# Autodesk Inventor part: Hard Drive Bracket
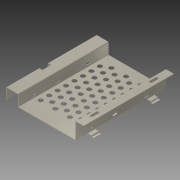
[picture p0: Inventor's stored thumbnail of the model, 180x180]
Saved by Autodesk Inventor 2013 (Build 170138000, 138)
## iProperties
Created: 2007-02
Part Number: Hard Drive Bracket
Material: Allgemein
Document SubType Name: Sheet Metal
Designer: Autodesk, Inc.
Mass: 29.7395 g
Surface Area: 618.59 cm^2
Volume: 29.7395 cm^3
Density: 1 g/cm^3
Flat Pattern Width: 16 cm
Flat Pattern Length: 21.3383 cm
Flat Pattern Area: 341.412 cm^2
Sheet Metal Rule: 1 mm
Sheet Metal Width: 160.000 mm
Sheet Metal Length: 213.383 mm
Sheet Metal Area: 34141.239 mm^2
Length: =<FLAT PATTERN LENGTH> cm
Width: =<FLAT PATTERN WIDTH> cm
Author: Autodesk, Inc.
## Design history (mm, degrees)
node "Face1"
node "Contour Flange1"
cut "Cut1" dims "d18" = 1 (= Thickness), "d19" = 0
node "Face3"
  sketch "Sketch5"
    geometry: L1 (0, 0)-(5.5, 0); L2 (6, -0.5)-(6, -0.5); L3 (7.5, -2)-(11, -2); A1 r 0.5 centre (5.5, -0.5) between (6, -0.5) and (5.5, 0); A2 r 1.5 centre (7.5, -0.5) between (6, -0.5) and (7.5, -2); 2 further points
    constraints: 6 end point, 4 point on circle, 4 point on line, 4 tangent, 2 centre point, 1 horizontal, 1 parallel, 1 perpendicular
    dimensions: "d67" = 2 distance of point (6, 0) point (6, -2); "d68" = 5 distance of point (6, -2) L3.end; "d69" = 0.5 radius of A1; "d70" = 1.5 radius of A2; "d71" = 5.5 distance of L1.start L1.end
node "Contour Flange2"
cut "Cut2" dims "d76" = 1 (= Thickness), "d77" = 0
mirror "Mirror1"
node "Contour Flange3"
cut "Cut3" dims "d101" = 1 (= Thickness), "d102" = 0
feature "iFeature1:1"
feature "iFeature2:1"
feature "iFeature3:1" dims "d118" = 3 (= d119), "d119" = 3, "d120" = 8
mirror "Mirror2"
feature "iFeature4:1"
body "Solid1"
node "Face2"
sketch "Sketch1"
  geometry: L1 (-50.5, 80)-(50.5, 80); L2 (50.5, 80)-(50.5, -80); L3 (50.5, -80)-(-50.5, -80); L4 (-50.5, -80)-(-50.5, 80); L5 (-50.5, -80)-(50.5, 80); 2 further points
  constraints: 10 end point, 2 parallel, 1 coincident, 1 horizontal, 1 midpoint, 1 perpendicular
  dimensions: "d0" = 101 distance of L1.start L1.end; "d1" = 160 distance of L3.end L1.start
face "Plate1" dims "Thickness" = 1
sketch "Sketch2"
  geometry: L1 (101, 0)-(101, 29); L2 (101, 29)-(116, 29)
  constraints: 4 end point, 1 perpendicular, 1 vertical
  dimensions: "d3" = 29 distance of L1.start L1.end (computed from Thickness); "d4" = 15 distance of L1.end L2.end
face "Plate2" dims "d5" = 1 (= BendReliefWidth), "d6" = 0.5 (= BendReliefDepth), "d7" = 2 (= MinimumRemnant), "d8" = 0.5 (= BendRadius), "d9" = 0.5 (= BendRadius), "d10" = 1, "d11" = 4 (= CornerReliefSize), "d12" = 1 (= Thickness), "d135" = 1 (= JacobiRadiusSize), "SeamGap" = 0.01, "Thickness" = 1
bend "Bend1" dims "d5" = 1 (= BendReliefWidth), "d6" = 0.5 (= BendReliefDepth), "d7" = 2 (= MinimumRemnant), "d8" = 0.5 (= BendRadius), "d9" = 0.5 (= BendRadius), "d10" = 1, "SeamGap" = 0.01, "Thickness" = 1
feature "Corner1" dims "d10" = 1, "d11" = 4 (= CornerReliefSize), "d12" = 1 (= Thickness), "d135" = 1 (= JacobiRadiusSize)
sketch "Sketch3"
  geometry: L1 (50, 80)-(51.477, 80) reference; L2 (50, -80)-(-50.5, -80) reference; L3 (-50.5, -80)-(-50.5, 80) reference; L4 (-50.5, 80)-(50, 80) reference; L5 (50, -80)-(51.477, -80) reference; L6 (51.477, -80)-(78.477, -80) reference; L7 (78.477, 80)-(51.477, 80) reference; L8 (78.477, -80)-(79.953, -80) reference; L9 (93.453, 80)-(79.953, 80) reference; L10 (79.953, 80)-(78.477, 80) reference; L11 (79.953, -80)-(93.453, -80) reference; L12 (93.453, 80)-(93.453, -80) reference; L13 (78.477, 80)-(78.477, -80) reference; L14 (79.953, 80)-(79.953, -80) reference; L15 (79.215, 80)-(79.215, -80) reference; L16 (50, -80)-(50, 80) reference; L17 (51.477, -80)-(51.477, 80) reference; L18 (50.738, -80)-(50.738, 80) reference; L19 (35, 60)-(58.477, 60); L20 (58.477, 60)-(58.477, 45); L21 (58.477, 45)-(35, 45); L22 (35, 45)-(35, 60)
  constraints: 8 end point, 2 parallel, 1 horizontal, 1 perpendicular
  dimensions: "d29" = 20 distance between parallel lines of L13 L20; "d30" = 15 distance between parallel lines of L16 L22; "d31" = 20 distance between parallel lines of L4 L19; "d32" = 15 distance of L21.end L19.start
sketch "Sketch4"
  geometry: L1 (-20, 140)-(-26.216, 140); L2 (-26.216, 139)-(-28.5, 139); L3 (-28.5, 139)-(-28.5, 126); L4 (-28.5, 126)-(-26.216, 126); L5 (-26.216, 125)-(-20, 125); L6 (-20, 125)-(-20, 140); L7 (-28.5, 125)-(-28.5, 140) reference; A1 r 0.5 centre (-26.216, 139.5) between (-26.216, 139) and (-26.216, 140); A2 r 0.5 centre (-26.216, 125.5) between (-26.216, 125) and (-26.216, 126)
  constraints: 12 end point, 4 point on circle, 4 tangent, 3 parallel, 2 centre point, 1 collinear, 1 horizontal
  dimensions: "d33" = 0.5 radius of A2; "d34" = 0.5 radius of A1 (= d33)
face "Plate4" dims "d35" = 0.5 (= BendRadius), "d38" = 2 (= MinimumRemnant), "SeamGap" = 0.01, "Thickness" = 1
bend "Bend2" dims "d35" = 0.5 (= BendRadius), "d36" = 1 (= BendReliefWidth), "d37" = 0.5 (= BendReliefDepth), "d38" = 2 (= MinimumRemnant), "d39" = 0.5 (= BendRadius), "SeamGap" = 0.01, "Thickness" = 1
face "Plate7" dims "d58" = 1 (= BendReliefWidth), "d59" = 0.5 (= BendReliefDepth), "d60" = 2 (= MinimumRemnant), "d61" = 0.5 (= BendRadius), "d62" = 0.5 (= BendRadius), "d63" = 1, "d64" = 4 (= CornerReliefSize), "d65" = 1 (= Thickness), "d136" = 1 (= JacobiRadiusSize), "SeamGap" = 0.01, "Thickness" = 1
bend "Bend3" dims "d58" = 1 (= BendReliefWidth), "d59" = 0.5 (= BendReliefDepth), "d60" = 2 (= MinimumRemnant), "d61" = 0.5 (= BendRadius), "d62" = 0.5 (= BendRadius), "d63" = 1, "SeamGap" = 0.01, "Thickness" = 1
feature "Corner4" dims "d63" = 1, "d64" = 4 (= CornerReliefSize), "d65" = 1 (= Thickness), "d136" = 1 (= JacobiRadiusSize)
sketch "Sketch6"
  geometry: L1 (-3, 139)-(-3, 126) reference; L2 (-6.5, 126)-(-3, 126) reference; L3 (-6.5, 139)-(-3, 139) reference; L4 (-8.5, 139)-(-8.5, 126) reference; L5 (-10.5, 139.5)-(-6, 139.5); L6 (-6, 139.5)-(-6, 125.5); L7 (-6, 125.5)-(-10.5, 125.5); L8 (-10.5, 125.5)-(-10.5, 139.5)
  constraints: 8 end point, 2 parallel, 1 horizontal, 1 perpendicular
  dimensions: "d72" = 3 distance between parallel lines of L1 L6; "d73" = 0.5 distance between parallel lines of L2 L7; "d74" = 0.5 distance between parallel lines of L5 L3; "d75" = 2 distance between parallel lines of L8 L4
sketch "Sketch7"
  geometry: L1 (0, 0)-(0, 20); L2 (0, 20)-(-22, 20); L3 (-22, 20)-(-22, 0)
  constraints: 6 end point, 1 parallel, 1 perpendicular, 1 vertical
  dimensions: "d86" = 20 distance of L1.start L1.end (computed from Thickness); "d87" = 22 distance of L1.end L2.end (computed from Thickness); "d88" = 20 distance of L2.end L3.end (= d86)
face "Plate8" dims "d78" = 1 (= BendReliefWidth), "d79" = 0.5 (= BendReliefDepth), "d80" = 2 (= MinimumRemnant), "d81" = 0.5 (= BendRadius), "d82" = 0.5 (= BendRadius), "d83" = 1, "d84" = 4 (= CornerReliefSize), "d85" = 1 (= Thickness), "d137" = 1 (= JacobiRadiusSize), "SeamGap" = 0.01, "Thickness" = 1
bend "Bend4" dims "d78" = 1 (= BendReliefWidth), "d79" = 0.5 (= BendReliefDepth), "d80" = 2 (= MinimumRemnant), "d81" = 0.5 (= BendRadius), "d82" = 0.5 (= BendRadius), "d83" = 1, "SeamGap" = 0.01, "Thickness" = 1
feature "Corner5" dims "d83" = 1, "d84" = 4 (= CornerReliefSize), "d85" = 1 (= Thickness), "d137" = 1 (= JacobiRadiusSize)
sketch "Sketch8"
  geometry: L1 (0, 88)-(10, 88); L2 (10, 88)-(10, 100); L3 (10, 100)-(0, 100); L4 (0, 100)-(0, 88); L5 (0, 160)-(-18.5, 160) reference; L6 (0, 0)-(0, 160) reference
  constraints: 8 end point, 2 parallel, 1 collinear, 1 horizontal, 1 perpendicular
  dimensions: "d89" = 12 distance of L1.end L2.end; "d90" = 10 distance of L1.start L1.end; "d91" = 60 distance between parallel lines of L5 L3
face "Plate9" dims "d92" = 0.5 (= BendRadius), "d95" = 2 (= MinimumRemnant), "SeamGap" = 0.01, "Thickness" = 1
bend "Bend5" dims "d92" = 0.5 (= BendRadius), "d93" = 1 (= BendReliefWidth), "d94" = 0.5 (= BendReliefDepth), "d95" = 2 (= MinimumRemnant), "d96" = 0.5 (= BendRadius), "SeamGap" = 0.01, "Thickness" = 1
sketch "Sketch9"
  geometry: L1 (28.5, 88)-(28.5, 100) reference; L2 (0, 0)-(18.5, 0) reference; L3 (18.5, 0)-(18.5, 88) reference; L4 (28.5, 100)-(18.5, 100) reference; L5 (18.5, 160)-(0, 160) reference; L6 (-1.477, 0)-(0, 0) reference; L7 (0, 160)-(-1.477, 160) reference; L8 (18.5, 88)-(28.5, 88) reference; L9 (18.5, 100)-(18.5, 160) reference; L10 (-1.477, 160)-(-20.477, 160) reference; L11 (-20.477, 0)-(-20.477, 160) reference; L12 (-20.477, 0)-(-1.477, 0) reference; L13 (0, 0)-(0, 160) reference; L14 (-1.477, 0)-(-1.477, 160) reference; L15 (-0.738, 0)-(-0.738, 160) reference; L16 (5, 86)-(-6.477, 86); L17 (-6.477, 86)-(-6.477, 102); L18 (-6.477, 102)-(5, 102); L19 (5, 102)-(5, 86)
  constraints: 8 end point, 2 parallel, 1 horizontal, 1 perpendicular
  dimensions: "d97" = 2 distance between parallel lines of L18 L4; "d98" = 2 distance between parallel lines of L16 L8 (= d97); "d99" = 5 distance between parallel lines of L14 L17; "d100" = 5 distance between parallel lines of L13 L19
sketch "Sketch10"
  geometry: L1 (18.5, 88)-(28.5, 88) reference; L2 (28.5, 88)-(28.5, 100) reference; 1 further point
  dimensions: "d103" = 6 distance from line of point (23.5, 94) L1; "d104" = 5 distance from line of point (23.5, 94) L2
sketch "Sketch11"
  geometry: L1 (27, 35)-(28.477, 35) reference; L2 (26.216, 21)-(27, 21) reference; L3 (28.477, 20)-(28.477, 0) reference; L4 (128.477, 160)-(28.477, 160) reference; L5 (27, 126)-(26.216, 126) reference; L6 (27, 21)-(27, 34) reference; L7 (27, 20)-(26.216, 20) reference; L8 (128.477, 0)-(128.477, 160) reference; L9 (27, 160)-(0, 160) reference; L10 (27, 126)-(27, 139) reference; L11 (28.477, 125)-(27, 125) reference; L12 (28.477, 125)-(28.477, 35) reference; L13 (28.477, 160)-(28.477, 140) reference; L14 (28.477, 140)-(43.477, 140) reference; L15 (43.477, 140)-(43.477, 125) reference; L16 (28.477, 35)-(43.477, 35) reference; L17 (27, 125)-(26.216, 125) reference; L18 (26.216, 140)-(27, 140) reference; L19 (27, 125)-(27, 35) reference; L20 (43.477, 125)-(28.477, 125) reference; L21 (27, 160)-(27, 140) reference; L22 (28.477, 0)-(128.477, 0) reference; L23 (43.477, 35)-(43.477, 20) reference; L24 (43.477, 20)-(28.477, 20) reference; L25 (27, 20)-(27, 0) reference; L26 (26.216, 35)-(27, 35) reference; L27 (26.216, 139)-(27, 139) reference; L28 (27, 34)-(26.216, 34) reference; L29 (0, 160)-(0, 0) reference; L30 (0, 0)-(27, 0) reference; L31 (27.738, 35)-(27.738, 125) reference; A1 r 0.5 centre (26.216, 139.5) between (26.216, 140) and (26.216, 139) reference; A2 r 0.5 centre (26.216, 20.5) between (26.216, 21) and (26.216, 20) reference; A3 r 0.5 centre (26.216, 34.5) between (26.216, 35) and (26.216, 34) reference; A4 r 0.5 centre (26.216, 125.5) between (26.216, 126) and (26.216, 125) reference; 1 further point
  dimensions: "d106" = 6 distance from line of L12 point (22.477, 131.5); "d107" = 28.5 distance from line of L9 point (22.477, 131.5)
sketch "Sketch12" dims "d116" = 10
  geometry: L1 (27, 125)-(26.216, 125) reference; L2 (27, 21)-(27, 34) reference; L3 (27, 34)-(26.216, 34) reference; L4 (26.216, 35)-(27, 35) reference; L5 (43.477, 20)-(28.477, 20) reference; L6 (43.477, 35)-(43.477, 20) reference; L7 (28.477, 35)-(43.477, 35) reference; L8 (43.477, 125)-(28.477, 125) reference; L9 (28.477, 0)-(128.477, 0) reference; L10 (128.477, 160)-(28.477, 160) reference; L11 (28.477, 160)-(28.477, 140) reference; L12 (28.477, 140)-(43.477, 140) reference; L13 (43.477, 140)-(43.477, 125) reference; L14 (27, 125)-(27, 35) reference; L15 (28.477, 125)-(28.477, 35) reference; L16 (0, 160)-(0, 0) reference; L17 (27, 20)-(27, 0) reference; L18 (27, 20)-(26.216, 20) reference; L19 (28.477, 20)-(28.477, 0) reference; L20 (26.216, 21)-(27, 21) reference; L21 (128.477, 0)-(128.477, 160) reference; L22 (28.477, 125)-(27, 125) reference; L23 (0, 0)-(27, 0) reference; L24 (27, 160)-(0, 160) reference; L25 (27, 160)-(27, 140) reference; L26 (26.216, 140)-(27, 140) reference; L27 (26.216, 139)-(27, 139) reference; L28 (27, 126)-(27, 139) reference; L29 (27, 126)-(26.216, 126) reference; L30 (27, 35)-(28.477, 35) reference; L31 (27.738, 35)-(27.738, 125) reference; A1 r 0.5 centre (26.216, 34.5) between (26.216, 35) and (26.216, 34) reference; A2 r 0.5 centre (26.216, 20.5) between (26.216, 21) and (26.216, 20) reference; A3 r 0.5 centre (26.216, 125.5) between (26.216, 126) and (26.216, 125) reference; A4 r 0.5 centre (26.216, 139.5) between (26.216, 140) and (26.216, 139) reference; A5 r 1.5 centre (22.477, 131.5) between (23.977, 131.5) and (23.977, 131.5) reference; 2 further points
  constraints: 1 vertical, 1 other
  dimensions: "d109" = 40.5 distance of point (22.477, 91) A5.centre; "d110" = 6 distance from line of point (22.477, 91) L15; "d113" = 55 distance of point (22.477, 91) point (22.477, 36)
sketch "Sketch13"
  geometry: L1 (109.93, 20)-(109.93, 80) reference; L2 (109.93, 80)-(91.43, 80) reference; L3 (70.953, -80)-(89.953, -80) reference; L4 (89.953, -80)-(89.953, 6) reference; L5 (89.953, 22)-(91.43, 22) reference; L6 (91.43, 80)-(89.953, 80) reference; L7 (91.43, 22)-(96.43, 22) reference; L8 (96.43, 22)-(96.43, 6) reference; L9 (96.43, 6)-(91.43, 6) reference; L10 (89.953, 80)-(70.953, 80) reference; L11 (91.43, -80)-(91.43, 6) reference; L12 (91.43, -80)-(109.93, -80) reference; L13 (57.5, 13.5)-(57.5, 8.5) reference; L14 (70.953, 80)-(69.477, 80) reference; L15 (69.477, -80)-(70.953, -80) reference; L16 (89.953, 6)-(84.953, 6) reference; L17 (84.953, 6)-(84.953, 22) reference; L18 (84.953, 22)-(89.953, 22) reference; L19 (119.93, 8)-(119.93, 20) reference; L20 (-35, -45)-(-35, -60) reference; L21 (-50, 45)-(-50, -45) reference; L22 (-35, 45)-(-50, 45) reference; L23 (51.477, -80)-(69.477, -80) reference; L24 (-50, 60)-(-35, 60) reference; L25 (-50, -45)-(-35, -45) reference; L26 (-35, -60)-(-50, -60) reference; L27 (-50, -80)-(50, -80) reference; L28 (50, -80)-(51.477, -80) reference; L29 (69.477, 80)-(51.477, 80) reference; L30 (-50, 80)-(-50, 60) reference; L31 (54.5, -46.5)-(54.5, -41.5) reference; L32 (-35, 60)-(-35, 45) reference; L33 (50, 80)-(-50, 80) reference; L34 (50, 80)-(51.477, 80) reference; L35 (119.93, 20)-(109.93, 20) reference; L36 (109.93, -80)-(109.93, 8) reference; L37 (109.93, 8)-(119.93, 8) reference; L38 (-50, -60)-(-50, -80) reference; L39 (57.5, -41.5)-(57.5, -46.5) reference; L40 (54.5, 8.5)-(54.5, 13.5) reference; L41 (50, -80)-(50, 80) reference; L42 (51.477, -80)-(51.477, 80) reference; L43 (69.477, -80)-(69.477, 80) reference; L44 (70.953, -80)-(70.953, 80) reference; L45 (89.953, 22)-(89.953, 80) reference; L46 (91.43, 22)-(91.43, 80) reference; L47 (70.215, -80)-(70.215, 80) reference; L48 (90.691, 22)-(90.691, 80) reference; L49 (50.738, 80)-(50.738, -80) reference; L50 (27.906, 42.5)-(40.897, 50); L51 (40.897, 50)-(40.897, 35); L52 (40.897, 35)-(27.906, 42.5); A1 r 2 centre (114.93, 14) between (116.93, 14) and (116.93, 14) reference; A2 r 1.5 centre (56, 51.5) between (54.5, 51.5) and (54.5, 51.5) reference; A3 r 1.5 centre (56, -46.5) between (54.5, -46.5) and (57.5, -46.5) reference; A4 r 1.5 centre (56, -41.5) between (57.5, -41.5) and (54.5, -41.5) reference; A5 r 1.5 centre (56, 8.5) between (54.5, 8.5) and (57.5, 8.5) reference; A6 r 1.5 centre (56, 13.5) between (57.5, 13.5) and (54.5, 13.5) reference; 49 further points
  constraints: 6 end point, 2 coincident, 1 horizontal, 1 vertical, 53 other
  dimensions: "d122" = 69.03307 distance from line of point (40.897, 50) L1; "d123" = 15 distance of L50.end L51.end; "d124" = 30 distance from line of L33 point (40.897, 50); "d125" = 12.99038 distance from line of point (27.906, 42.5) L51 (derived); "d128" = 15 distance of point (27.906, 42.5) point (27.906, 27.5); "d131" = 25.98076 distance of point (27.906, 42.5) point (1.925, 42.5) (= 2 x d125)
feature "Definition1" dims "d0" = 1 (derived)
other parameters: "BendRadius" = 0.5, "BendReliefWidth" = 1 (= Thickness), "BendReliefDepth" = 0.5 (= 0.5 x Thickness), "CornerReliefSize" = 4 (= 4 x Thickness), "MinimumRemnant" = 2 (= 2 x Thickness), "TransitionRadius" = 0.5 (= BendRadius), "JacobiRadiusSize" = 1 (= Thickness), "d2" = 0.5 (= BendRadius), "d105" = 0, "d108" = 0, "d121" = 90 deg, "d134" = 0, "GapSize" = 1 (= Thickness), "BendRadius" = 0.5, "BendReliefDepth" = 0.5, "BendReliefWidth" = 1, "CornerReliefSize" = 4, "JacobiRadiusSize" = 1, "MinimumRemnant" = 2, "Thickness" = 1, "TransitionRadius" = 0.5, "GapSize" = 1
